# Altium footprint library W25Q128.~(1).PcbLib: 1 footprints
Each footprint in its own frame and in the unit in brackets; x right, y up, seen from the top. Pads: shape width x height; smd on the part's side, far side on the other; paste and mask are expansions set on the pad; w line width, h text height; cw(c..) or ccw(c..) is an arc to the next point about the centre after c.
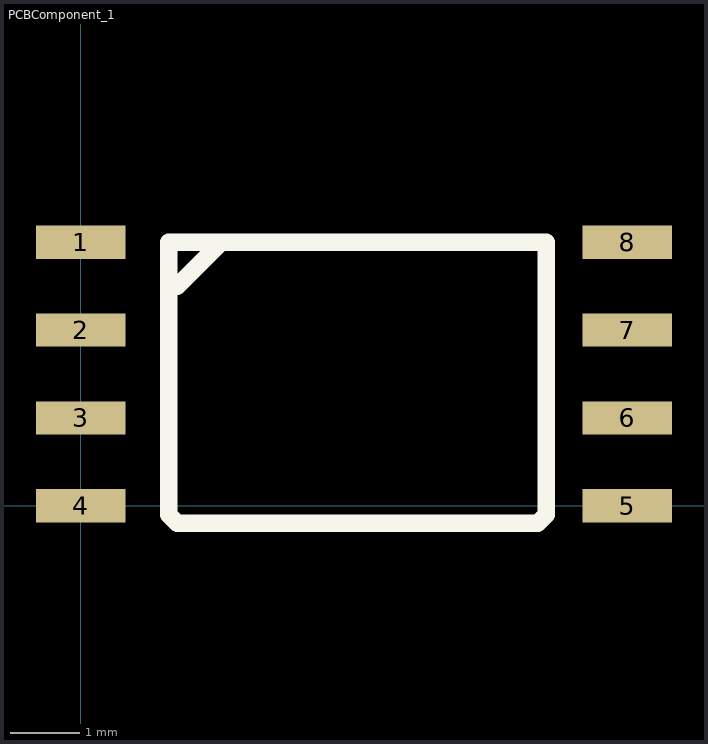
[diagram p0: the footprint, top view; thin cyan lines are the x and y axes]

## PCBComponent_1 [mm]
pads (8):
  rect 1.3x0.48 all layers, no hole: 1(0,3.81) 2(0,2.54) 3(0,1.27) 4(0,0) 5(7.9,0) 6(7.9,1.27) 7(7.9,2.54) 8(7.9,3.81)
Top Overlay:
  lines w0.254: 1.27,2.921 1.27,3.048 ; 1.397,3.175 2.032,3.81 ; 1.27,-0.127 1.397,-0.254 6.604,-0.254 6.731,-0.127 6.731,3.81 1.27,3.81 1.27,-0.127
